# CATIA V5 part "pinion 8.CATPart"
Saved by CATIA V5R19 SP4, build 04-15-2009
Part number: pinion 8
Bounding box of the stored display mesh (mm): x 0 to 22.15, y -24.147 to 24.147, z -23.971 to 23.971
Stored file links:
  G:\EU_thinkMotion\CFAO_2010\MMS_groupe1\MMS_groupe1\A reprendre\OK\rdeneffle\pinion 8.CATPart
  G:\EU_thinkMotion\CFAO_2010\MMS_groupe1\MMS_groupe1\A reprendre\OK\rdeneffle\pinion 2.CATPart
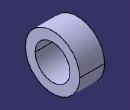
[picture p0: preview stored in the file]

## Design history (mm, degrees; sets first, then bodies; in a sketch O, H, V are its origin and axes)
Parameters
  `rayon interieur.1` = 15.505 mm
  `rayon extérieur.1` = 24.147 mm
Body1 (main body)
Body2
  Sketch1 on yz-plane, origin (0, 0, 0), H (0, 1, 0), V (0, 0, 1)
    circle A1 centre (0, 0) radius 15.505
    circle A2 centre (0, 0) radius 24.147
    radius A2 = 24.147 {= `rayon extérieur.1`}
    radius A1 = 15.505 {= `rayon interieur.1`}
  Pad1: profile Sketch1, direction (1, 0, 0), length 22.15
